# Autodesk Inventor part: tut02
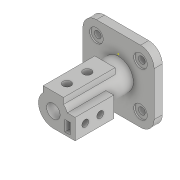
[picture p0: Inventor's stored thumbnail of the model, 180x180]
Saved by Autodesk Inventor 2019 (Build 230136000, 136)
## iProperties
Created: 2015-03
Part Number: tut02
Material: Generic
Document SubType Name: Modeling
Designer: Sandeep
Density: 1 g/cm^3
Appearance: Default
Author: Sandeep
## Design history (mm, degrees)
sketch "Sketch1"
  geometry: L1 (-32.5, -52.5)-(32.5, -52.5); L2 (52.5, -32.5)-(52.5, 32.5); L3 (32.5, 52.5)-(-32.5, 52.5); L4 (-52.5, 32.5)-(-52.5, -32.5); L5 (-52.5, -52.5)-(52.5, 52.5); L6 (52.5, -52.5)-(-52.5, 52.5); A1 r 20 centre (32.5, 32.5) between (52.5, 32.5) and (32.5, 52.5); A2 r 20 centre (32.5, -32.5) between (32.5, -52.5) and (52.5, -32.5); A3 r 20 centre (-32.5, -32.5) between (-52.5, -32.5) and (-32.5, -52.5); A4 r 20 centre (-32.5, 32.5) between (-32.5, 52.5) and (-52.5, 32.5); 1 further point
  constraints: 12 end point, 8 point on circle, 8 point on line, 8 tangent, 4 centre point, 2 equal radius, 2 midpoint, 2 parallel, 1 horizontal, 1 perpendicular
  dimensions: "d0" = 105 distance of L6.start L5.end; "d1" = 105 distance of L5.start L6.start; "d2" = 20 radius of A1; "d3" = 20 radius of A2
extrude "Extrusion1" new body sketch "Sketch1" distance "d4" = 12; taper "d5" = 0 deg
hole "Hole1" diameter "d8" = 10; stored, may be unused: countersink angle "d12" = 90 deg, drill point angle "d14" = 118 deg; dims "d9" = 6, "d10" = 20, "d11" = 2, "d13" = 8, "d15" = 10, "d16" = 10
hole "Hole2" diameter "d19" = 10; stored, may be unused: countersink angle "d23" = 90 deg, drill point angle "d25" = 118 deg; dims "d17" = 10, "d18" = 10, "d20" = 6, "d21" = 20, "d22" = 2, "d24" = 8
hole "Hole3" diameter "d28" = 10; stored, may be unused: countersink angle "d32" = 90 deg, drill point angle "d34" = 118 deg; dims "d26" = 10, "d27" = 10, "d29" = 6, "d30" = 20, "d31" = 2, "d33" = 8
hole "Hole4" diameter "d37" = 10; stored, may be unused: countersink angle "d41" = 90 deg, drill point angle "d43" = 118 deg; dims "d35" = 10, "d36" = 10, "d38" = 6, "d39" = 20, "d40" = 2, "d42" = 8
sketch "Sketch2"
  geometry: C1 r 22 at (0, 0); 1 further point
  constraints: 1 centre point, 1 coincident
  dimensions: "d44" = 44 diameter of C1
extrude "Extrusion2" join sketch "Sketch2" distance "d45" = 96; taper "d46" = 0 deg
sketch "Sketch3"
  geometry: L1 (-15, 16.093)-(-15, 25); L2 (15, 16.093)-(15, 25); L3 (-15, 25)-(15, 25); L4 (0, 0)-(20.619, 0); L5 (0, 6.043)-(0, 0); A1 r 22 centre (0, 0) between (15, 16.093) and (-15, 16.093); 1 further point
  constraints: 10 end point, 3 vertical, 2 horizontal, 2 point on circle, 1 centre point, 4 other
  dimensions: "d48" = 25 distance from line of point (0, 0) L3; "d49" = 30 distance of L1.end L2.end
extrude "Extrusion3" join sketch "Sketch3" distance "d51" = 76; taper "d52" = 0 deg
sketch "Sketch4"
  geometry: L1 (20.494, 8)-(32, 8); L2 (32, 8)-(32, -22); L3 (0, 0)-(37.067, 0); L4 (0, -22)-(32, -22); A1 r 22 centre (0, 0) between (20.494, 8) and (0, -22) reference; A2 r 22 centre (0, 0) between (0, -22) and (20.494, 8); 1 further point
  constraints: 8 end point, 5 point on circle, 2 horizontal, 2 perpendicular, 1 centre point, 1 concentric, 1 tangent
  dimensions: "d53" = 30 distance of L2.end L1.end; "d54" = 32 distance from line of L2 point (0, 0)
extrude "Extrusion4" join sketch "Sketch4" distance "d55" = 57; taper "d56" = 0 deg
sketch "Sketch5"
  geometry: L1 (17, -2)-(25, -2); L2 (25, -2)-(25, -18); L3 (25, -18)-(17, -18); L4 (17, -18)-(17, -2); 1 further point
  constraints: 8 end point, 2 parallel, 1 horizontal, 1 perpendicular
  dimensions: "d57" = 16 distance of L1.end L2.end; "d58" = 2 distance from line of point (0, 0) L1; "d59" = 25 distance from line of point (0, 0) L2; "d60" = 8 distance of L2.end L3.end
extrude "Extrusion5" cut sketch "Sketch5" distance "d61" = 50; taper "d62" = 0 deg
sketch "Sketch6"
  geometry: 1 further point
sketch "Sketch8"
  geometry: 1 further point
hole "Hole10" diameter "d113" = 10; stored, may be unused: countersink angle "d117" = 90 deg, drill point angle "d119" = 118 deg; dims "d111" = 15, "d112" = 15, "d114" = 6, "d115" = 4, "d116" = 2, "d118" = 96
hole "Hole11" diameter "d122" = 10; stored, may be unused: countersink angle "d126" = 90 deg, drill point angle "d128" = 118 deg; dims "d120" = 37, "d121" = 15, "d123" = 6, "d124" = 4, "d125" = 2, "d127" = 96
sketch "Sketch9"
  geometry: C1 r 10 at (0, 0); 1 further point
  constraints: 1 centre point, 1 coincident
  dimensions: "d129" = 20 diameter of C1
extrude "Extrusion7" cut sketch "Sketch9" distance "d130" = 96; taper "d131" = 0 deg
sketch "Sketch10"
  geometry: L1 (15, -0.369)-(15, 146.33); L2 (30, 0)-(30, 76) reference; L3 (0, 0)-(30, 0) reference; C1 r 6 at (15, 20); C2 r 6 at (15, 50); 1 further point
  constraints: 2 centre point, 2 end point, 2 point on line, 1 equal radius, 1 vertical
  dimensions: "d132" = 15 distance between parallel lines of L1 L2; "d133" = 12 diameter of C1; "d134" = 20 distance from line of C1.centre L3; "d135" = 30 distance of C2.centre C1.centre
extrude "Extrusion8" cut sketch "Sketch10" stored distance "d136" = 96; taper "d137" = 0 deg
body "Solid1"
